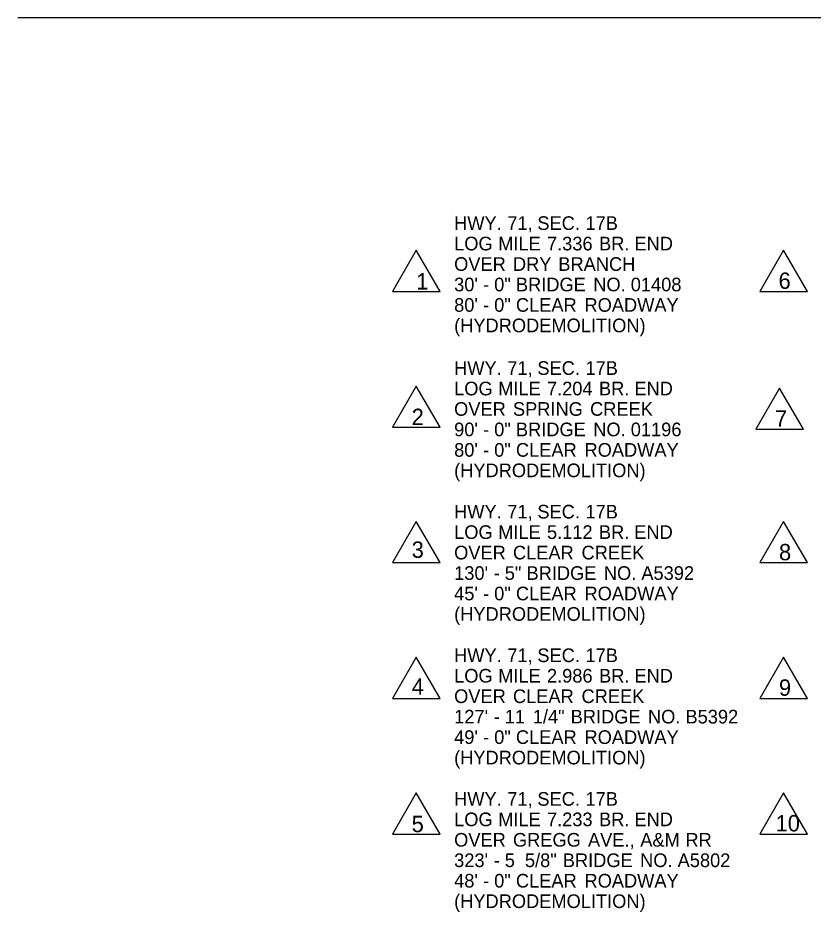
# Model space of a CAD drawing. Extents: x 1930579 to 1935271, y 596413 to 597442.
# Drawn here: x 1933675 to 1934259, y 596594 to 597250 of the extents above; entities that cross this region are included whole.
import ezdxf

# ---------------------------------------------------------------- set-up
doc = ezdxf.new("R2010")
doc.units = 0
doc.layers.add('Default', color=7, linetype='Continuous')
doc.layers.add('R_Border', color=7, linetype='Continuous')

msp = doc.modelspace()

# ---------------------------------------------------------------- linework, layer by layer
at = {"layer": 'R_Border'}
for p, q in [((1935270.78, 597250.04), (1933675.42, 597250.04)), ((1933993.39, 597106.55), (1933993.39, 597106.55)), ((1933967.6, 597079.6), (1933950.19, 597049.44)), ((1933985.02, 597049.44), (1933967.6, 597079.6)), ((1934236.97, 597079.6), (1934219.56, 597049.44)), ((1934254.39, 597049.44), (1934236.97, 597079.6)), ((1933950.19, 597049.44), (1933985.02, 597049.44)), ((1934219.56, 597049.44), (1934254.39, 597049.44)), ((1933967.6, 596980.03), (1933950.19, 596949.87)), ((1933985.02, 596949.87), (1933967.6, 596980.03)), ((1934234.04, 596978.62), (1934216.62, 596948.46)), ((1934251.45, 596948.46), (1934234.04, 596978.62)), ((1933950.19, 596949.87), (1933985.02, 596949.87)), ((1934216.62, 596948.46), (1934251.45, 596948.46)), ((1933967.6, 596880.82), (1933950.19, 596850.66)), ((1933985.02, 596850.66), (1933967.6, 596880.82)), ((1934236.97, 596880.82), (1934219.56, 596850.66)), ((1934254.39, 596850.66), (1934236.97, 596880.82)), ((1933950.19, 596850.66), (1933985.02, 596850.66)), ((1934219.56, 596850.66), (1934254.39, 596850.66)), ((1933967.6, 596781.26), (1933950.19, 596751.1)), ((1933985.02, 596751.1), (1933967.6, 596781.26)), ((1934236.97, 596781.26), (1934219.56, 596751.1)), ((1934254.39, 596751.1), (1934236.97, 596781.26)), ((1933950.19, 596751.1), (1933985.02, 596751.1)), ((1934219.56, 596751.1), (1934254.39, 596751.1)), ((1933967.6, 596681.8), (1933950.19, 596651.64)), ((1933985.02, 596651.64), (1933967.6, 596681.8)), ((1934236.97, 596681.8), (1934219.56, 596651.64)), ((1934254.39, 596651.64), (1934236.97, 596681.8)), ((1933950.19, 596651.64), (1933985.02, 596651.64)), ((1934219.56, 596651.64), (1934254.39, 596651.64))]:
    msp.add_line(p, q, dxfattribs=at)

# ---------------------------------------------------------------- texts
at = {"layer": 'Default'}
for s, p in [('HWY.', (1933995.34, 597094.55)), (' 71,', (1934030.59, 597094.55)), (' SEC.', (1934052.65, 597094.55)), (' 17B', (1934087.92, 597094.55)), ('LOG', (1933995.34, 597079.55)), (' MILE', (1934023.96, 597079.55)), (' 7.336', (1934059.7, 597079.55)), (' BR.', (1934097.9, 597079.55)), (' END', (1934123.85, 597079.55)), ('OVER', (1933995.34, 597064.55)), (' BRANCH', (1934068.03, 597064.55)), (' DRY', (1934034.75, 597064.55)), ("30'", (1933995.34, 597049.55)), (' 0"', (1934020.98, 597049.55)), (' BRIDGE', (1934036.93, 597049.55)), (' NO.', (1934093.64, 597049.55)), (' 01408', (1934121.14, 597049.55)), (' -', (1934012.88, 597049.55)), ("80'", (1933995.34, 597034.55)), (' 0"', (1934020.98, 597034.55)), (' CLEAR', (1934036.93, 597034.55)), (' ROADWAY', (1934087.21, 597034.55)), (' -', (1934012.88, 597034.55)), ('(HYDRODEMOLITION)', (1933995.34, 597019.55)), ('HWY.', (1933995.34, 596988.28)), (' 71,', (1934030.59, 596988.28)), (' SEC.', (1934052.65, 596988.28)), (' 17B', (1934087.92, 596988.28)), ('LOG', (1933995.34, 596973.28)), (' MILE', (1934023.96, 596973.28)), (' 7.204', (1934059.7, 596973.28)), (' BR.', (1934097.85, 596973.28)), (' END', (1934123.8, 596973.28)), ('OVER', (1933995.34, 596958.28)), (' SPRING', (1934034.75, 596958.28)), (' CREEK', (1934091.33, 596958.28)), ("90'", (1933995.34, 596943.28)), (' 0"', (1934020.98, 596943.28)), (' BRIDGE', (1934036.93, 596943.28)), (' NO.', (1934093.64, 596943.28)), (' 01196', (1934121.14, 596943.28)), (' -', (1934012.88, 596943.28)), ("80'", (1933995.34, 596928.28)), (' 0"', (1934020.98, 596928.28)), (' CLEAR', (1934036.93, 596928.28)), (' ROADWAY', (1934087.21, 596928.28)), (' -', (1934012.88, 596928.28)), ('(HYDRODEMOLITION)', (1933995.34, 596913.28)), ('HWY.', (1933995.34, 596882.98)), (' 71,', (1934030.59, 596882.98)), (' SEC.', (1934052.65, 596882.98)), (' 17B', (1934087.92, 596882.98)), ('LOG', (1933995.34, 596867.98)), (' MILE', (1934023.96, 596867.98)), (' 5.112', (1934059.7, 596867.98)), (' BR.', (1934097.79, 596867.98)), (' END', (1934123.74, 596867.98)), ('OVER', (1933995.34, 596852.98)), (' CLEAR', (1934034.75, 596852.98)), (' CREEK', (1934085.03, 596852.98)), ("130'", (1933995.34, 596837.98)), (' 5"', (1934028.74, 596837.98)), (' BRIDGE', (1934044.7, 596837.98)), (' NO.', (1934101.4, 596837.98)), (' A5392', (1934128.9, 596837.98)), (' -', (1934020.65, 596837.98)), ("45'", (1933995.34, 596822.98)), (' 0"', (1934020.98, 596822.98)), (' CLEAR', (1934036.93, 596822.98)), (' ROADWAY', (1934087.21, 596822.98)), (' -', (1934012.88, 596822.98)), ('(HYDRODEMOLITION)', (1933995.34, 596807.98)), ('HWY.', (1933995.34, 596777.68)), (' 71,', (1934030.59, 596777.68)), (' SEC.', (1934052.65, 596777.68)), (' 17B', (1934087.92, 596777.68)), ('LOG', (1933995.34, 596762.68)), (' MILE', (1934023.96, 596762.68)), (' 2.986', (1934059.7, 596762.68)), (' BR.', (1934097.9, 596762.68)), (' END', (1934123.85, 596762.68)), ('OVER', (1933995.34, 596747.68)), (' CLEAR', (1934034.75, 596747.68)), (' CREEK', (1934085.03, 596747.68)), ("127'", (1933995.34, 596732.68)), (' 11', (1934028.74, 596732.68)), ('  1/4"', (1934045.59, 596732.68)), (' BRIDGE', (1934077.07, 596732.68)), (' NO.', (1934133.77, 596732.68)), (' B5392', (1934161.27, 596732.68)), (' -', (1934020.65, 596732.68)), ("49'", (1933995.34, 596717.68)), (' 0"', (1934020.98, 596717.68)), (' CLEAR', (1934036.93, 596717.68)), (' ROADWAY', (1934087.21, 596717.68)), (' -', (1934012.88, 596717.68)), ('(HYDRODEMOLITION)', (1933995.34, 596702.68)), ('HWY.', (1933995.34, 596672.38)), (' 71,', (1934030.59, 596672.38)), (' SEC.', (1934052.65, 596672.38)), (' 17B', (1934087.92, 596672.38)), ('LOG', (1933995.34, 596657.38)), (' MILE', (1934023.96, 596657.38)), (' 7.233', (1934059.7, 596657.38)), (' BR.', (1934097.9, 596657.38)), (' END', (1934123.85, 596657.38)), ('OVER', (1933995.34, 596642.38)), (' GREGG', (1934034.75, 596642.38)), (' AVE.,', (1934089.77, 596642.38)), (' A&M', (1934128.13, 596642.38)), (' RR', (1934161.24, 596642.38)), ("323'", (1933995.34, 596627.38)), (' 5', (1934028.74, 596627.38)), ('  5/8"', (1934039.83, 596627.38)), (' BRIDGE', (1934071.31, 596627.38)), (' NO.', (1934128.02, 596627.38)), (' A5802', (1934155.52, 596627.38)), (' -', (1934020.65, 596627.38)), ("48'", (1933995.34, 596612.38)), (' 0"', (1934020.98, 596612.38)), (' CLEAR', (1934036.93, 596612.38)), (' ROADWAY', (1934087.21, 596612.38)), (' -', (1934012.88, 596612.38)), ('(HYDRODEMOLITION)', (1933995.34, 596597.38))]:
    msp.add_text(s, height=10, rotation=360, dxfattribs=at).set_placement(p)
at = {"layer": 'R_Border'}
for s, p in [('1', (1933967.6, 597050.88)), ('6', (1934233.24, 597051.35)), ('2', (1933964.2, 596951.49)), ('7', (1934230.64, 596950.37)), ('3', (1933964.2, 596854.13)), ('8', (1934233.57, 596852.34)), ('4', (1933964.2, 596753.71)), ('9', (1934233.52, 596753.01)), ('5', (1933964.2, 596653.01)), ('10', (1934231.07, 596653.55))]:
    msp.add_text(s, height=12, rotation=360, dxfattribs=at).set_placement(p)

doc.saveas('drawing.dxf')
